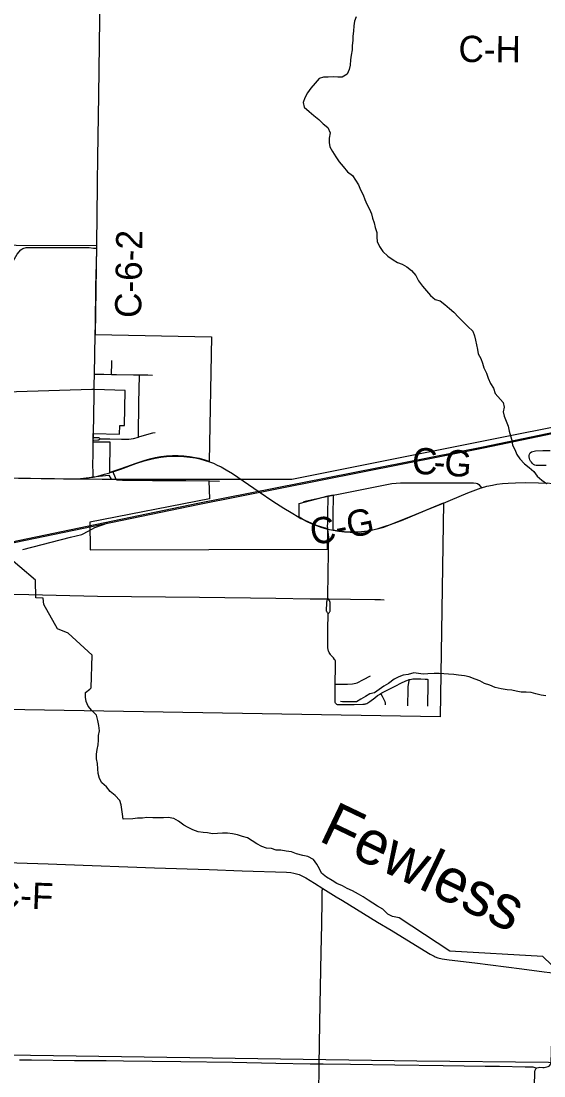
# Model space of a CAD drawing. Extents: x -21.7 to 34, y 0 to 22.
# Drawn here: x 27.989 to 29.12, y 16.19 to 18.47 of the extents above; entities that cross this region are included whole.
import ezdxf

# ---------------------------------------------------------------- set-up
doc = ezdxf.new("R2010")
doc.units = 0
for name, color, linetype in [('GM_X_City_Street', 7, 'Continuous'), ('GM_X_Corporation', 7, 'Continuous'), ('GM_X_County_Road', 7, 'Continuous'), ('GM_X_County_Road_Text', 7, 'Continuous'), ('GM_X_Minor_River', 7, 'Continuous'), ('GM_X_Minor_River_Text', 7, 'Continuous'), ('GM_X_Rail_Line', 7, 'Continuous'), ('GM_X_State_Route', 7, 'Continuous'), ('GM_X_Township_Road', 7, 'Continuous'), ('GM_X_US_Route', 7, 'Continuous')]:
    doc.layers.add(name, color=color, linetype=linetype)

msp = doc.modelspace()

# ---------------------------------------------------------------- linework, layer by layer
at = {"layer": 'GM_X_City_Street'}
for points in [[(27.9411, 17.8971), (27.9473, 17.9079), (27.953, 17.9174), (27.9576, 17.9263), (27.9598, 17.9314), (27.9695, 17.9456), (27.9806, 17.9661), (27.9887, 17.9752), (27.9933, 17.9786), (28.0007, 17.9802), (28.0207, 17.9807), (28.0889, 17.9806), (28.1363, 17.9803), (28.146, 17.9794), (28.1529, 17.9789)], [(28.1853, 17.7061), (28.1853, 17.7112), (28.1856, 17.7263), (28.1856, 17.7361)], [(28.1482, 17.7067), (28.1539, 17.7066), (28.1681, 17.7064), (28.1853, 17.7061), (28.1955, 17.706), (28.2327, 17.7055), (28.2453, 17.7053), (28.2638, 17.7051), (28.2737, 17.7047)], [(28.2432, 17.5708), (28.2432, 17.5788), (28.2434, 17.6012), (28.2438, 17.618), (28.2442, 17.641), (28.245, 17.6778), (28.2453, 17.7002), (28.2453, 17.7053)], [(28.1607, 17.5671), (28.1678, 17.5668), (28.1816, 17.5666), (28.2065, 17.5661), (28.2165, 17.566), (28.2227, 17.5663), (28.2277, 17.5669), (28.2325, 17.5679), (28.2432, 17.5708), (28.2439, 17.571), (28.2666, 17.5779), (28.2744, 17.5798), (28.2793, 17.5809)], [(28.1456, 17.5644), (28.1471, 17.5644), (28.1555, 17.5645), (28.1562, 17.5646), (28.1569, 17.5648), (28.1576, 17.565), (28.1582, 17.5653), (28.1588, 17.5657), (28.1595, 17.5662), (28.1607, 17.5671)], [(28.1457, 17.5699), (28.1468, 17.5699), (28.1553, 17.5699), (28.1561, 17.5699), (28.1569, 17.5697), (28.1581, 17.5692), (28.1591, 17.5685), (28.1607, 17.5671)], [(28.6532, 17.2209), (28.6527, 17.2286), (28.6527, 17.2314), (28.6535, 17.2702), (28.6545, 17.328), (28.655, 17.3541), (28.6531, 17.3717), (28.6525, 17.3798), (28.6527, 17.3829), (28.653, 17.3952), (28.653, 17.4106), (28.6535, 17.4352), (28.6537, 17.4431)], [(27.9298, 17.232), (27.953, 17.2314), (28.0059, 17.2302), (28.0649, 17.2289), (28.1548, 17.2271), (28.3755, 17.2243), (28.5402, 17.2222), (28.6147, 17.2209), (28.6427, 17.2209), (28.6532, 17.2209), (28.6551, 17.2208), (28.7017, 17.22), (28.7546, 17.2196), (28.7669, 17.2193), (28.7746, 17.2189)], [(28.6539, 17.1886), (28.6529, 17.19), (28.6523, 17.1908), (28.6515, 17.192), (28.6509, 17.1933), (28.6503, 17.1954), (28.6502, 17.1961), (28.6501, 17.1981), (28.6505, 17.2104), (28.6506, 17.213), (28.6507, 17.2141), (28.6509, 17.2149), (28.6513, 17.2168), (28.6517, 17.2183), (28.6532, 17.2209)], [(28.6539, 17.1886), (28.6551, 17.1899), (28.6561, 17.1912), (28.6567, 17.1921), (28.6575, 17.1935), (28.6577, 17.1941), (28.6579, 17.1949), (28.658, 17.1956), (28.6581, 17.1963), (28.6582, 17.1978), (28.6583, 17.209), (28.658, 17.2122), (28.6578, 17.2136), (28.6576, 17.2146), (28.6572, 17.2157), (28.6566, 17.2167), (28.6563, 17.2173), (28.6554, 17.2185), (28.6548, 17.2193), (28.6532, 17.2209)], [(28.6716, 16.9935), (28.6705, 16.9945), (28.6698, 16.9952), (28.6695, 16.9958), (28.6691, 16.9967), (28.6688, 16.9979), (28.6687, 16.9991), (28.6687, 17.0024), (28.6689, 17.0173), (28.6691, 17.033), (28.6691, 17.0364), (28.6697, 17.0763), (28.6695, 17.084), (28.6692, 17.0865), (28.6686, 17.0882), (28.6677, 17.0899), (28.6649, 17.0932), (28.6596, 17.0993), (28.6586, 17.1007), (28.6558, 17.1051), (28.655, 17.1067), (28.6543, 17.1085), (28.6539, 17.1102), (28.6535, 17.112), (28.6532, 17.1139), (28.6531, 17.1155), (28.6529, 17.1183), (28.6529, 17.1388), (28.6532, 17.155), (28.6539, 17.1886)], [(28.6691, 17.0364), (28.6785, 17.0366), (28.6953, 17.0368), (28.7065, 17.0372), (28.7102, 17.0377), (28.7132, 17.0384), (28.7167, 17.0398), (28.73, 17.0466), (28.7453, 17.0549)], [(28.6716, 16.9935), (28.673, 16.9928), (28.6738, 16.9925), (28.6749, 16.9923), (28.6769, 16.9923), (28.6797, 16.9923), (28.7096, 16.9929), (28.7288, 16.9933), (28.7308, 16.9934), (28.7326, 16.9936), (28.7339, 16.9939), (28.735, 16.9942), (28.7373, 16.9951), (28.7395, 16.9962), (28.7436, 16.999), (28.7545, 17.0073), (28.7605, 17.0118), (28.7631, 17.0135), (28.7647, 17.0145), (28.7658, 17.0152), (28.7679, 17.0165), (28.7699, 17.0177), (28.7888, 17.0273), (28.7999, 17.033), (28.8109, 17.0387), (28.8216, 17.0436), (28.8241, 17.0446), (28.8274, 17.0459), (28.8291, 17.0464), (28.831, 17.0469), (28.8338, 17.0475), (28.8365, 17.0479), (28.8415, 17.0483), (28.8471, 17.0482), (28.8545, 17.0479), (28.8638, 17.0476), (28.8653, 17.0475), (28.8668, 17.0474), (28.8678, 17.0472), (28.8687, 17.0469), (28.8692, 17.0465)], [(28.826, 16.9899), (28.826, 16.9943), (28.8264, 17.0212), (28.8264, 17.0237), (28.8266, 17.0311), (28.8272, 17.036), (28.8286, 17.0436), (28.8291, 17.0464)], [(28.8695, 16.9891), (28.8694, 17.0058), (28.8698, 17.0225), (28.87, 17.0325), (28.87, 17.0398), (28.87, 17.0423), (28.8699, 17.0436), (28.8698, 17.0451), (28.8697, 17.0458), (28.8692, 17.0465)], [(28.778, 16.9922), (28.778, 16.9934), (28.7779, 16.9946), (28.7778, 16.9956), (28.7777, 16.9963), (28.7772, 16.9975), (28.7769, 16.9981), (28.7714, 17.0098), (28.7679, 17.0165)]]:
    msp.add_lwpolyline(points, dxfattribs=at)
at = {"layer": 'GM_X_Corporation'}
for points in [[(27.804, 17.9866), (28.1528, 17.9852), (28.1494, 17.7925), (28.4011, 17.7877), (28.3966, 17.5178), (28.3964, 17.5179), (28.3875, 17.5209), (28.3754, 17.5241), (28.3663, 17.5261), (28.354, 17.5281), (28.3415, 17.5295), (28.3291, 17.5302), (28.3166, 17.5302), (28.3041, 17.5295), (28.2917, 17.5281), (28.2794, 17.5259), (28.2672, 17.5231), (28.2552, 17.5197), (28.2375, 17.5139), (28.2052, 17.5023), (28.1817, 17.4943), (28.1822, 17.5594), (28.1452, 17.5598), (28.1456, 17.5782), (28.202, 17.5768), (28.2027, 17.596), (28.2129, 17.5957), (28.2148, 17.6716), (28.1474, 17.6736), (28.1422, 17.6735), (27.8857, 17.666)], [(27.8922, 17.4841), (28.0809, 17.4806), (28.1026, 17.4807), (28.1181, 17.4814), (28.1305, 17.4825), (28.137, 17.4834), (28.1448, 17.4848), (28.1791, 17.4886), (28.184, 17.4798), (28.1942, 17.4801), (28.1958, 17.4792), (28.1973, 17.4789), (28.2464, 17.478), (28.3956, 17.4762), (28.3969, 17.437), (28.138, 17.3869), (28.1385, 17.3273), (28.6519, 17.3285), (28.6528, 17.3723), (28.64, 17.3759), (28.6283, 17.3799), (28.6168, 17.3845), (28.6055, 17.3897), (28.5981, 17.3936), (28.5946, 17.3955), (28.5907, 17.3977), (28.5908, 17.4273), (28.6535, 17.4436), (28.6645, 17.4458), (28.6643, 17.4353), (28.6638, 17.4107), (28.6638, 17.3953), (28.6635, 17.3699), (28.6762, 17.3678), (28.6886, 17.3665), (28.7009, 17.3659), (28.7133, 17.3659), (28.7257, 17.3667), (28.738, 17.3682), (28.7391, 17.3684), (28.7501, 17.3705), (28.7617, 17.3733), (28.7791, 17.3786), (28.7887, 17.3819), (28.8118, 17.3911), (28.8351, 17.4006), (28.9029, 17.4288), (28.8958, 16.966), (27.9107, 16.9822)]]:
    msp.add_lwpolyline(points, dxfattribs=at)
at = {"layer": 'GM_X_County_Road'}
for p, q in [((28.1478, 17.6826), (28.1482, 17.7067)), ((28.1476, 17.6739), (28.1478, 17.6826)), ((28.1455, 17.5592), (28.1456, 17.5644)), ((28.3972, 17.4759), (28.4186, 17.4757)), ((28.6003, 17.4317), (28.6537, 17.4431))]:
    msp.add_line(p, q, dxfattribs=at)
for points in [[(28.153, 17.9846), (28.1531, 17.9926), (28.1537, 18.0454), (28.155, 18.1199), (28.1556, 18.1758), (28.1574, 18.3094), (28.1597, 18.474), (28.1596, 18.4872)], [(28.1496, 17.793), (28.15, 17.8125), (28.1514, 17.8964), (28.1524, 17.9461), (28.1529, 17.9777), (28.1529, 17.9789), (28.153, 17.9846)], [(28.1482, 17.7067), (28.1496, 17.792), (28.1496, 17.793)], [(28.1458, 17.5767), (28.1458, 17.5776), (28.1474, 17.6604), (28.1476, 17.6729), (28.1476, 17.6739)], [(28.1451, 17.4842), (28.145, 17.4927), (28.1447, 17.5113), (28.145, 17.5331), (28.1455, 17.5592)], [(28.1456, 17.5644), (28.1457, 17.5699), (28.1458, 17.5767)], [(28.188, 17.4959), (28.1929, 17.483), (28.1935, 17.4815), (28.194, 17.4803), (28.1944, 17.4795)], [(28.1944, 17.4795), (28.1952, 17.4789), (28.1963, 17.4785), (28.1976, 17.4783), (28.2042, 17.478), (28.2084, 17.4778), (28.2737, 17.4772), (28.3972, 17.4759)], [(28.6537, 17.4431), (28.6648, 17.4453), (28.676, 17.4475), (28.7732, 17.4669), (28.7915, 17.4701), (28.8006, 17.4712), (28.8099, 17.4716), (28.8471, 17.4716), (28.9091, 17.4715), (28.9525, 17.4716), (28.9679, 17.4715), (28.974, 17.4709), (28.9769, 17.4702), (28.9797, 17.468), (28.9827, 17.4644), (28.9856, 17.4609)], [(27.8411, 16.6564), (27.8559, 16.6551), (27.862, 16.6544), (27.8775, 16.6536), (27.9799, 16.6504), (28.0482, 16.6479), (28.0855, 16.6464), (28.2779, 16.6398), (28.3959, 16.636), (28.4673, 16.6333), (28.5636, 16.63), (28.5729, 16.6293), (28.5791, 16.6283), (28.5852, 16.6268), (28.5912, 16.6248), (28.5969, 16.6222), (28.6052, 16.6177), (28.6238, 16.6065), (28.6423, 16.595)], [(28.6423, 16.595), (28.6713, 16.577), (28.6846, 16.5692), (28.7606, 16.5222), (28.7897, 16.5045), (28.8613, 16.4608), (28.8745, 16.4528), (28.8827, 16.4484), (28.8855, 16.4472), (28.8913, 16.4453), (28.9002, 16.4431), (28.9155, 16.4406), (28.9711, 16.4342), (29.0725, 16.421), (29.1213, 16.415), (29.1335, 16.4133), (29.1397, 16.4122), (29.1413, 16.4117)], [(29.1044, 16.2067), (29.1054, 16.2075), (29.1087, 16.2082), (29.1119, 16.2083), (29.1182, 16.208), (29.1212, 16.2081), (29.1242, 16.2084), (29.1271, 16.2091), (29.1298, 16.2102), (29.1322, 16.2118), (29.1341, 16.214), (29.1353, 16.2165), (29.136, 16.2193), (29.1364, 16.2223), (29.1368, 16.2378), (29.1376, 16.272), (29.1392, 16.3497), (29.14, 16.3808), (29.1413, 16.4117)], [(29.0896, 15.7041), (29.0923, 15.775), (29.0934, 15.8153), (29.0948, 15.8432), (29.0949, 15.8534), (29.0953, 15.8687), (29.0957, 15.8839), (29.0966, 15.9068), (29.097, 15.9317), (29.0975, 15.9781), (29.0981, 16.0154), (29.099, 16.0683), (29.0997, 16.1398), (29.0999, 16.1678), (29.1009, 16.1989), (29.1013, 16.2021), (29.1026, 16.2053), (29.1044, 16.2067)]]:
    msp.add_lwpolyline(points, dxfattribs=at)
at = {"layer": 'GM_X_Minor_River'}
for points in [[(28.7142, 18.4795), (28.7105, 18.4697), (28.7092, 18.4595), (28.7086, 18.4481), (28.7069, 18.4372)], [(28.7069, 18.4372), (28.707, 18.4277), (28.7053, 18.4174), (28.7055, 18.4079), (28.7038, 18.3966), (28.702, 18.386), (28.7014, 18.375), (28.6993, 18.3652), (28.695, 18.3554), (28.6842, 18.3488), (28.6744, 18.3486), (28.6642, 18.3492), (28.6539, 18.349), (28.6437, 18.3484), (28.6342, 18.3456), (28.6256, 18.3359), (28.6159, 18.3251), (28.6093, 18.3146), (28.6034, 18.3041), (28.5994, 18.2943), (28.6018, 18.2836), (28.6127, 18.2746), (28.6227, 18.2657), (28.6335, 18.2571), (28.6432, 18.2482), (28.6532, 18.2396), (28.6579, 18.2285), (28.6558, 18.2172), (28.6556, 18.2077), (28.6573, 18.1982), (28.6628, 18.1882), (28.6705, 18.1763), (28.6775, 18.1655), (28.686, 18.1555), (28.6953, 18.1439), (28.7065, 18.1361), (28.7131, 18.126), (28.7193, 18.1161), (28.724, 18.1053), (28.7295, 18.0946), (28.7331, 18.0846), (28.737, 18.0743), (28.7429, 18.0636), (28.7472, 18.0536), (28.7497, 18.0441), (28.7529, 18.0341), (28.7554, 18.0238), (28.7589, 18.0131), (28.7587, 18.0029), (28.7597, 17.9934), (28.7651, 17.983), (28.7717, 17.9722), (28.7825, 17.9621), (28.7941, 17.9536), (28.8038, 17.9484), (28.814, 17.9444), (28.8237, 17.9389), (28.8342, 17.9307), (28.8431, 17.9199), (28.8493, 17.9088), (28.8577, 17.8972), (28.8663, 17.8872), (28.8748, 17.8767), (28.8852, 17.8682), (28.8957, 17.8649), (28.9058, 17.8575), (28.9159, 17.8486), (28.9259, 17.8404), (28.936, 17.83), (28.9449, 17.8203), (28.956, 17.8094), (28.9664, 17.7997), (28.97, 17.7898), (28.9725, 17.7799), (28.9766, 17.76), (28.9779, 17.7505), (28.9838, 17.7409), (28.9878, 17.7306), (28.9906, 17.7203), (28.996, 17.7091), (29, 17.6984), (29.0051, 17.6862), (29.0113, 17.6762), (29.0152, 17.6647), (29.0323, 17.6454), (29.0343, 17.6355), (29.0323, 17.6256), (29.0343, 17.6157), (29.043, 17.5943), (29.045, 17.5836), (29.0483, 17.5737), (29.0507, 17.5638), (29.0528, 17.5535), (29.0575, 17.5439), (29.0622, 17.5331), (29.0685, 17.5235), (29.0785, 17.5127), (29.0886, 17.5053), (29.0986, 17.4963), (29.106, 17.4859), (29.116, 17.4774)], [(29.116, 17.4774), (29.1258, 17.4707), (29.1284, 17.4718)], [(28.141, 17.0285), (28.1432, 17.0995), (28.0915, 17.1468), (28.0682, 17.1564), (28.0389, 17.209), (28.0373, 17.2227), (28.021, 17.2234), (28.0203, 17.2614), (27.9528, 17.3193), (27.9311, 17.4063)], [(29.1246, 17.0117), (29.1147, 17.0131), (29.103, 17.0156), (29.0929, 17.0184), (29.0823, 17.0194), (29.0709, 17.0196), (29.0607, 17.0218), (29.0509, 17.0235), (29.0407, 17.0241), (29.0282, 17.0266), (29.015, 17.0295), (29.0034, 17.0343), (28.9917, 17.0383), (28.982, 17.0435), (28.9718, 17.0475), (28.9587, 17.0523), (28.9489, 17.0544), (28.936, 17.0562), (28.9258, 17.0575), (28.9141, 17.0581), (28.9039, 17.0591), (28.8936, 17.0593), (28.8827, 17.0599), (28.8694, 17.059), (28.8592, 17.0585), (28.8489, 17.0594), (28.8391, 17.0611), (28.8269, 17.0572), (28.8163, 17.0559), (28.8064, 17.0527), (28.7968, 17.0476), (28.7841, 17.0383), (28.7742, 17.0325), (28.7642, 17.0251), (28.7538, 17.0177), (28.7439, 17.0156), (28.7343, 17.0101), (28.7247, 17.0038), (28.7151, 16.9987), (28.7057, 16.9981), (28.6954, 16.9984), (28.6845, 16.9986), (28.6807, 16.999)], [(28.7927, 16.5343), (28.7829, 16.5395), (28.7718, 16.5499), (28.7605, 16.5566), (28.7505, 16.5633), (28.7403, 16.5696), (28.7291, 16.5766), (28.7194, 16.5825), (28.7063, 16.5896), (28.6946, 16.5952), (28.6849, 16.6003), (28.6721, 16.6059), (28.6624, 16.6121), (28.6504, 16.6192), (28.6396, 16.6278), (28.6352, 16.6374), (28.6294, 16.6474), (28.622, 16.6574), (28.61, 16.6644), (28.5987, 16.6662), (28.5855, 16.6699), (28.5746, 16.6739), (28.5625, 16.6757), (28.5516, 16.6774), (28.5413, 16.678), (28.5308, 16.6816), (28.5202, 16.6818), (28.51, 16.6858), (28.4992, 16.6917), (28.4895, 16.698), (28.479, 16.7043), (28.4684, 16.7072), (28.4575, 16.7112), (28.4466, 16.7133), (28.436, 16.7146), (28.4254, 16.7145), (28.4144, 16.7136), (28.4034, 16.7134), (28.3928, 16.7151), (28.383, 16.7157), (28.3728, 16.7174), (28.3611, 16.7215), (28.351, 16.7266), (28.3412, 16.7321), (28.3297, 16.7407), (28.3199, 16.7462), (28.3079, 16.7487), (28.2976, 16.7478), (28.2859, 16.7473), (28.2745, 16.7479), (28.2616, 16.7485), (28.2521, 16.7472), (28.2411, 16.7467), (28.2309, 16.7454), (28.2104, 16.745), (28.2091, 16.7553), (28.2074, 16.7656), (28.2061, 16.7755), (28.2033, 16.7854), (28.1932, 16.7959), (28.1824, 16.8044), (28.1739, 16.8148), (28.1642, 16.823), (28.1591, 16.8326), (28.1563, 16.8437), (28.1557, 16.8539), (28.1545, 16.8654), (28.1528, 16.8749), (28.1526, 16.8855), (28.1539, 16.8954), (28.156, 16.9052), (28.1566, 16.9158), (28.1568, 16.9257), (28.1589, 16.9359), (28.1576, 16.9469), (28.1555, 16.9583), (28.1527, 16.9694), (28.1423, 16.9795), (28.1342, 16.9892), (28.1298, 16.9991), (28.1285, 17.0086), (28.1287, 17.0185), (28.1383, 17.0257), (28.141, 17.0285)], [(30.0798, 16.2411), (29.911, 16.3049), (29.7523, 16.2511), (29.6478, 16.2931), (29.5065, 16.2891), (29.4512, 16.3354), (29.2827, 16.3901), (29.2146, 16.4332), (29.1372, 16.4298), (29.1179, 16.4481), (28.917, 16.4597), (28.807, 16.5314), (28.7927, 16.5343)]]:
    msp.add_lwpolyline(points, dxfattribs=at)
at = {"layer": 'GM_X_Rail_Line'}
for points in [[(23.5167, 16.459), (23.6295, 16.4808), (23.9621, 16.5465), (24.6321, 16.6797), (25.2774, 16.8081), (25.8901, 16.9293), (26.3845, 17.0293), (27.0776, 17.1675), (27.7467, 17.2984), (28.3715, 17.4275), (28.9889, 17.5495), (29.6221, 17.6814), (30.2791, 17.8098), (30.3167, 17.8172)], [(23.5167, 16.4567), (23.6289, 16.4784), (23.9619, 16.5433), (24.6317, 16.6775), (25.2779, 16.8058), (25.8906, 16.927), (26.3849, 17.0271), (27.078, 17.1653), (27.7471, 17.2961), (28.3719, 17.4252), (28.9894, 17.5472), (29.6225, 17.6791), (30.2796, 17.8076), (30.3167, 17.8149)], [(25.8905, 16.9443), (26.7077, 17.1083), (26.7688, 17.1586), (26.8119, 17.2101), (26.8634, 17.276), (26.8946, 17.3324), (26.9509, 17.3923), (27.006, 17.4474), (27.0347, 17.4689), (27.0802, 17.4809), (27.5534, 17.4838), (27.9584, 17.4827), (28.1647, 17.4796), (28.575, 17.4796), (29.0617, 17.5773), (30.0904, 17.7802), (30.3167, 17.8248)], [(27.9928, 17.3274), (28.0965, 17.3543), (28.1206, 17.3603), (28.1356, 17.3684), (28.1486, 17.3755), (28.1775, 17.385)], [(25.8774, 16.2608), (26.0821, 16.258), (27.0998, 16.252), (27.5176, 16.2418), (28.8453, 16.222), (29.9847, 16.211), (30.3167, 16.2074)]]:
    msp.add_lwpolyline(points, dxfattribs=at)
at = {"layer": 'GM_X_State_Route'}
msp.add_line((28.6531, 17.3717), (28.6642, 17.3693), dxfattribs=at)
for points in [[(28.188, 17.4959), (28.2055, 17.5017), (28.2377, 17.5133), (28.2554, 17.5191), (28.2675, 17.5225), (28.2796, 17.5253), (28.2919, 17.5275), (28.3043, 17.529), (28.3168, 17.5297), (28.3293, 17.5296), (28.3418, 17.5289), (28.3542, 17.5275), (28.3665, 17.5255), (28.3757, 17.5236), (28.3877, 17.5203), (28.3968, 17.5173)], [(28.3968, 17.5173), (28.4054, 17.514), (28.4139, 17.5102), (28.4224, 17.5061), (28.4333, 17.5), (28.4465, 17.4918), (28.4698, 17.4763), (28.5044, 17.4527)], [(28.1451, 17.4842), (28.1551, 17.4863), (28.1701, 17.4902), (28.1811, 17.4935)], [(28.1811, 17.4935), (28.182, 17.4938), (28.188, 17.4959)], [(27.8843, 17.4837), (27.8925, 17.4835), (27.935, 17.4829), (28.0811, 17.4801), (28.1029, 17.4802), (28.1184, 17.4808), (28.1307, 17.482), (28.1429, 17.4838), (28.1451, 17.4842)], [(28.9856, 17.4609), (28.9969, 17.4643), (29.0091, 17.4671), (29.0183, 17.4688), (29.0307, 17.4704), (29.0431, 17.4714), (29.0587, 17.4721), (29.0805, 17.4724), (29.1085, 17.472), (29.1572, 17.4706)], [(28.5044, 17.4527), (28.5341, 17.4325), (28.5575, 17.4173), (28.5733, 17.4074), (28.59, 17.3977)], [(28.9031, 17.4282), (28.9183, 17.4346), (28.9557, 17.45), (28.9732, 17.4567), (28.985, 17.4607), (28.9856, 17.4609)], [(28.6642, 17.3693), (28.6765, 17.3673), (28.6888, 17.366), (28.7012, 17.3653), (28.7135, 17.3654), (28.7259, 17.3661), (28.7382, 17.3677), (28.7394, 17.3679), (28.7504, 17.3699), (28.7624, 17.3728), (28.7743, 17.3763), (28.7889, 17.3814), (28.8121, 17.3905), (28.8638, 17.4118), (28.9031, 17.4282)], [(28.59, 17.3977), (28.5909, 17.3972), (28.5948, 17.3949), (28.5984, 17.393), (28.6058, 17.3891), (28.617, 17.3839), (28.6285, 17.3794), (28.6403, 17.3754), (28.6531, 17.3717)]]:
    msp.add_lwpolyline(points, dxfattribs=at)
at = {"layer": 'GM_X_Township_Road'}
for points in [[(29.1251, 17.5095), (29.1036, 17.5093), (29.1007, 17.5102), (29.098, 17.5117), (29.0956, 17.5138), (29.0935, 17.5162), (29.0917, 17.5189), (29.0902, 17.5217), (29.0891, 17.5246), (29.0885, 17.5277), (29.0886, 17.5308), (29.0894, 17.5339), (29.091, 17.5365), (29.0935, 17.5385), (29.0963, 17.5398), (29.0993, 17.5406), (29.1024, 17.541), (29.1181, 17.5414), (29.1338, 17.5416)], [(28.6345, 16.216), (28.6352, 16.2556), (28.636, 16.3053), (28.6389, 16.4576), (28.6401, 16.5167), (28.6408, 16.5695), (28.6409, 16.5887), (28.641, 16.5909), (28.6416, 16.5928), (28.6423, 16.595)], [(27.9858, 16.2242), (28.0118, 16.2245), (28.105, 16.2234), (28.1734, 16.2227), (28.2107, 16.2221), (28.3351, 16.2209), (28.447, 16.2191), (28.5402, 16.2173), (28.6148, 16.216), (28.6345, 16.216)], [(28.6193, 15.4619), (28.6194, 15.4707), (28.6201, 15.4889), (28.6201, 15.4983), (28.6206, 15.5168), (28.6219, 15.6006), (28.6226, 15.6285), (28.6241, 15.6907), (28.6254, 15.7334), (28.6252, 15.7458), (28.6254, 15.7582), (28.6262, 15.7955), (28.6281, 15.8794), (28.6291, 15.9292), (28.6306, 16.0131), (28.6317, 16.0628), (28.6323, 16.1095), (28.6333, 16.1467), (28.6345, 16.216)], [(28.6345, 16.216), (28.6428, 16.216), (28.7019, 16.2151), (28.7982, 16.2135), (28.9026, 16.2122), (28.993, 16.2108), (29.0241, 16.2106), (29.08, 16.2095), (29.0926, 16.2095), (29.0938, 16.2095), (29.0955, 16.2094), (29.0968, 16.2092), (29.0983, 16.2088), (29.1006, 16.2081), (29.1025, 16.2074), (29.1044, 16.2067)]]:
    msp.add_lwpolyline(points, dxfattribs=at)
at = {"layer": 'GM_X_US_Route'}
msp.add_line((28.6531, 17.3717), (28.6642, 17.3693), dxfattribs=at)
for points in [[(28.188, 17.4959), (28.2055, 17.5017), (28.2377, 17.5133), (28.2554, 17.5191), (28.2675, 17.5225), (28.2796, 17.5253), (28.2919, 17.5275), (28.3043, 17.529), (28.3168, 17.5297), (28.3293, 17.5296), (28.3418, 17.5289), (28.3542, 17.5275), (28.3665, 17.5255), (28.3757, 17.5236), (28.3877, 17.5203), (28.3968, 17.5173)], [(28.3968, 17.5173), (28.4054, 17.514), (28.4139, 17.5102), (28.4224, 17.5061), (28.4333, 17.5), (28.4465, 17.4918), (28.4698, 17.4763), (28.5044, 17.4527)], [(28.1451, 17.4842), (28.1551, 17.4863), (28.1701, 17.4902), (28.1811, 17.4935)], [(28.1811, 17.4935), (28.182, 17.4938), (28.188, 17.4959)], [(27.8843, 17.4837), (27.8925, 17.4835), (27.935, 17.4829), (28.0811, 17.4801), (28.1029, 17.4802), (28.1184, 17.4808), (28.1307, 17.482), (28.1429, 17.4838), (28.1451, 17.4842)], [(28.9856, 17.4609), (28.9969, 17.4643), (29.0091, 17.4671), (29.0183, 17.4688), (29.0307, 17.4704), (29.0431, 17.4714), (29.0587, 17.4721), (29.0805, 17.4724), (29.1085, 17.472), (29.1572, 17.4706)], [(28.5044, 17.4527), (28.5341, 17.4325), (28.5575, 17.4173), (28.5733, 17.4074), (28.59, 17.3977)], [(28.9031, 17.4282), (28.9183, 17.4346), (28.9557, 17.45), (28.9732, 17.4567), (28.985, 17.4607), (28.9856, 17.4609)], [(28.6642, 17.3693), (28.6765, 17.3673), (28.6888, 17.366), (28.7012, 17.3653), (28.7135, 17.3654), (28.7259, 17.3661), (28.7382, 17.3677), (28.7394, 17.3679), (28.7504, 17.3699), (28.7624, 17.3728), (28.7743, 17.3763), (28.7889, 17.3814), (28.8121, 17.3905), (28.8638, 17.4118), (28.9031, 17.4282)], [(28.59, 17.3977), (28.5909, 17.3972), (28.5948, 17.3949), (28.5984, 17.393), (28.6058, 17.3891), (28.617, 17.3839), (28.6285, 17.3794), (28.6403, 17.3754), (28.6531, 17.3717)]]:
    msp.add_lwpolyline(points, dxfattribs=at)

# ---------------------------------------------------------------- texts
at = {"layer": 'GM_X_County_Road_Text'}
for s, height, rotation, p in [('C-H', 0.05682, 359.6023, (28.9355, 18.3816)), ('C-6-2', 0.05682, 89.1132, (28.2491, 17.8279)), ('C', 0.0568, 358.6101, (28.8348, 17.4908)), ('G', 0.0568, 355.6103, (28.9034, 17.488)), ('-', 0.0568, 355.6945, (28.8804, 17.4897)), ('C-G', 0.05682, 11.4643, (28.6206, 17.3361)), ('C-F', 0.05682, 357.7986, (27.9316, 16.5542))]:
    msp.add_text(s, height=height, rotation=rotation, dxfattribs=at).set_placement(p)
at = {"layer": 'GM_X_Minor_River_Text'}
msp.add_text('Fewless', height=0.09477, rotation=334.4532, dxfattribs=at).set_placement((28.6304, 16.6993))

doc.saveas('drawing.dxf')
